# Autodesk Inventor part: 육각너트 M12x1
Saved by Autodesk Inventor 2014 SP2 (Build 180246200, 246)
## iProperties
Created: 2024-04
Part Number: 육각너트 M12x1
Material: Generic
Document SubType Name: Modeling
Designer: Administrator
Density: 1 g/cm^3
Appearance: Default
Author: Administrator
Author: jhkim
Description: 6각 너트 및 6각 가는 너트
Creation Date: 2024-04-08
Sending System: Autodesk Inventor 2025
Preprocessor: ST-DEVELOPER v20
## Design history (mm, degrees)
node "육각너트 M12x11"
body "Solid1"
node "기준1"
